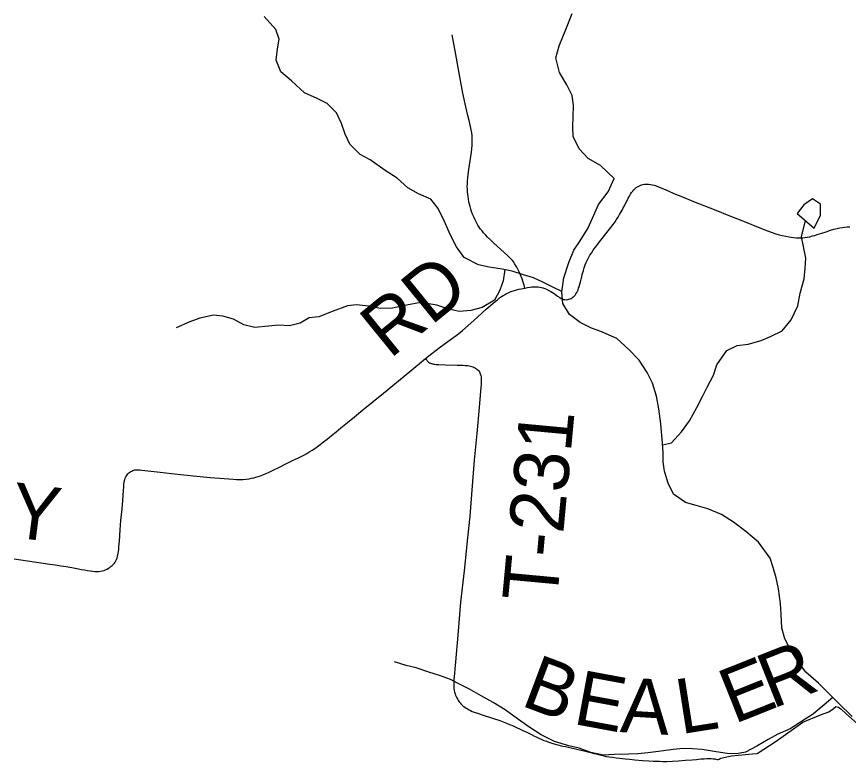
# Model space of a CAD drawing. Extents: x 1451455 to 1749751, y 218250 to 574981.
# Drawn here: x 1587271 to 1591819, y 293624 to 297697 of the extents above; entities that cross this region are included whole.
import ezdxf

# ---------------------------------------------------------------- set-up
doc = ezdxf.new("R2010")
doc.units = 0
for name, color, linetype in [('GM_X_Minor_Lake', 7, 'Continuous'), ('GM_X_Minor_River', 7, 'Continuous'), ('GM_X_Township_Road', 7, 'Continuous'), ('GM_X_Township_Road_Text', 7, 'Continuous'), ('GM_X_Township_ROW', 7, 'Continuous')]:
    doc.layers.add(name, color=color, linetype=linetype)

msp = doc.modelspace()

# ---------------------------------------------------------------- linework, layer by layer
at = {"layer": 'GM_X_Minor_Lake'}
for points in [[(1591632, 296539.6), (1591666.9, 296611.2), (1591665.7, 296671.3), (1591622, 296699.9), (1591575.6, 296668.5), (1591538.9, 296621)], [(1591538.9, 296621), (1591632, 296539.6)]]:
    msp.add_lwpolyline(points, dxfattribs=at)
at = {"layer": 'GM_X_Minor_River'}
for points in [[(1591840, 293869.1), (1591764.9, 293942.1), (1591707.5, 293999), (1591656.2, 294051.7), (1591586.8, 294110.7), (1591543.5, 294167.3), (1591500.4, 294237.9), (1591471.1, 294294.4), (1591455.8, 294352.6), (1591450.8, 294428.7), (1591447.5, 294486.8), (1591436.5, 294567), (1591423.3, 294627.2), (1591408, 294683.5), (1591390.6, 294735.8), (1591327.7, 294822.7), (1591258.4, 294881.6), (1591191, 294932.6), (1591125.4, 294973.5), (1591049.8, 295004.5), (1590986, 295023.4), (1590928.1, 295040.2), (1590862.6, 295085.1), (1590833.4, 295145.5), (1590814.2, 295211.8), (1590806.8, 295262), (1590805.5, 295312), (1590802.1, 295364.1), (1590793.5, 295470.3), (1590782.5, 295552.5), (1590769.4, 295620.7), (1590748.3, 295693), (1590719, 295751.5), (1590675.8, 295818.1), (1590618.5, 295876.9), (1590553.2, 295935.8), (1590465.7, 295975), (1590413.9, 295993.7), (1590352.2, 296024.6), (1590294.7, 296067.4), (1590257.4, 296127.9), (1590252.3, 296192), (1590263.2, 296267.9), (1590290.3, 296351.6), (1590317.2, 296419.3), (1590351.9, 296470.8), (1590394.8, 296538.3), (1590419.6, 296594), (1590452.6, 296669.6), (1590505.5, 296738.9), (1590538.5, 296812.5), (1590463.3, 296883.6), (1590395.7, 296920.5), (1590346.4, 296973.2), (1590313.2, 297041.7), (1590311.9, 297093.7), (1590314.6, 297149.7), (1590315.4, 297211.7), (1590308.1, 297265.8), (1590278.8, 297324.3), (1590239.6, 297390.8), (1590218.6, 297471.1), (1590237.5, 297536.9), (1590274.7, 297626.5), (1590307.8, 297714.1)], [(1590252.5, 296193.5), (1590202.5, 296216.7), (1590148.8, 296245.4), (1590097.1, 296268.1), (1590043.2, 296284.9), (1589981.5, 296305.7), (1589925.5, 296316.5), (1589855.6, 296327.4), (1589795.7, 296340.2), (1589718.2, 296379.3), (1589676.9, 296437.9), (1589643.7, 296502.4), (1589608.7, 296580.9), (1589575.5, 296647.3), (1589536.1, 296697.9), (1589468.4, 296728.8), (1589410.8, 296761.6), (1589351.4, 296814.4), (1589285.9, 296855.3), (1589204.6, 296914.5), (1589148.9, 296943.2), (1589093.6, 297000), (1589068.2, 297054.4), (1589047, 297112.7), (1589019.7, 297171.1), (1588968.3, 297221.8), (1588914.6, 297248.5), (1588844.9, 297279.5), (1588773.7, 297346.5), (1588716.3, 297395.2), (1588691.1, 297459.6), (1588697.9, 297521.5), (1588706.6, 297573.5), (1588689.3, 297627.7), (1588624.1, 297698.6)], [(1590802.7, 295355.2), (1590852.2, 295365.4), (1590907, 295426.7), (1590949.8, 295486.2), (1590990.8, 295559.7), (1591021.6, 295619.3), (1591048.3, 295675), (1591081.2, 295736.6), (1591099.9, 295792.4), (1591155, 295871.7), (1591211.4, 295898.9), (1591271.5, 295906.1), (1591341.8, 295925.2), (1591392.2, 295948.5), (1591456.6, 295977.7), (1591505.4, 296039.1), (1591542.4, 296114.6), (1591555.3, 296184.5), (1591576.3, 296262.2), (1591583.1, 296322.2), (1591585.8, 296376.2), (1591572.6, 296440.4), (1591563.3, 296492.5), (1591583.8, 296581.7)], [(1589940.9, 296313.5), (1589930.7, 296252.4), (1589914, 296200.6), (1589883.3, 296146.9), (1589816.7, 296105.8), (1589754.5, 296090.6), (1589690.3, 296083.5), (1589628.5, 296098.3), (1589568.7, 296119.1), (1589480.8, 296134.3), (1589402.5, 296119.4), (1589326.3, 296102.4), (1589260.2, 296101.3), (1589194.3, 296114.2), (1589130.3, 296121), (1589080.2, 296115.7), (1589001.8, 296086.8), (1588923.3, 296055.8), (1588871.2, 296050.5), (1588820.7, 296021.1), (1588762.5, 296005.9), (1588702.5, 296008.7), (1588648.4, 296003.5), (1588574.2, 295996.5), (1588514.3, 296011.3), (1588456.7, 296042), (1588398.8, 296058.8), (1588346.9, 296063.5), (1588272.6, 296048.5), (1588218.3, 296027.2), (1588143.8, 295994.2)], [(1591734.4, 293972.3), (1591628, 293884), (1591557.4, 293838.9), (1591500.8, 293801.6), (1591432.4, 293772.5), (1591380, 293743.2), (1591317.4, 293706), (1591257, 293674.8), (1591206.8, 293665.5), (1591156.8, 293666.1), (1591096.8, 293675), (1591018.9, 293688), (1590967, 293692.7), (1590914.9, 293693.4), (1590860.8, 293688.1), (1590780.6, 293677.2), (1590722.4, 293670), (1590668.3, 293664.7), (1590616.3, 293663.4), (1590538.1, 293660.5), (1590480, 293657.3), (1590410.2, 293672.2), (1590346.4, 293695.1), (1590290.5, 293707.9), (1590212.8, 293732.9), (1590139.2, 293768), (1590077.6, 293808.8), (1590010.1, 293855.8), (1589942.7, 293904.7), (1589877.2, 293945.6), (1589811.6, 293982.5), (1589748, 294019.4), (1589696.3, 294044.1), (1589642.6, 294070.9), (1589582.8, 294093.7), (1589525, 294112.5), (1589455.2, 294135.4), (1589401.3, 294148.2), (1589337.5, 294169)]]:
    msp.add_lwpolyline(points, dxfattribs=at)
at = {"layer": 'GM_X_Township_Road'}
for points in [[(1590049.5, 296212.7), (1590046.3, 296228), (1590043.2, 296239.3), (1590039.7, 296250.6), (1590035.4, 296262.7), (1590030.2, 296274.9), (1590024.1, 296288.8), (1590018.5, 296301.8), (1590011.9, 296316.1), (1590005.9, 296327.4), (1589999.4, 296338.3), (1589994.2, 296346.9), (1589989.4, 296353.9), (1589983.8, 296361.3), (1589977.2, 296368.6), (1589969.9, 296376), (1589954.2, 296390.8), (1589936.9, 296406.8), (1589880.4, 296457.2), (1589863.1, 296473.7), (1589846.6, 296490.2), (1589836.6, 296501.4), (1589824.4, 296514.5), (1589815.8, 296524.9), (1589807.5, 296535.3), (1589801, 296544.8), (1589793.6, 296557), (1589785.8, 296571.7), (1589778.9, 296586.1), (1589771.5, 296601.7), (1589764.6, 296616.9), (1589758.9, 296631.7), (1589754.1, 296644.3), (1589750.2, 296658.1), (1589747.2, 296671.2), (1589744.2, 296684.6), (1589741.6, 296699.4), (1589739.8, 296713.3), (1589737, 296739.4), (1589735.9, 296754.1), (1589735.3, 296768.8), (1589735.5, 296782.7), (1589736.2, 296798.2), (1589737.6, 296814.4), (1589739.4, 296833.5), (1589742.9, 296860.4), (1589746.8, 296885.6), (1589750.6, 296908.7)], [(1590049.5, 296212.7), (1590064.8, 296215.4), (1590079.2, 296217.4), (1590088.9, 296218.4), (1590095, 296218.8), (1590100.7, 296219.2), (1590111.1, 296219.2), (1590122.3, 296218.8), (1590131, 296217.9), (1590140.1, 296216.2), (1590148.8, 296213.6), (1590158.8, 296210.1), (1590169.2, 296205.8), (1590180.9, 296199.7), (1590192.2, 296193.2), (1590210, 296181.9), (1590229.1, 296168.9), (1590240.4, 296161.1), (1590249.1, 296155.9), (1590255.6, 296152.8), (1590261.7, 296150.7), (1590269.1, 296149.3), (1590276.9, 296148.9), (1590284.3, 296149.3), (1590291.2, 296151.1), (1590296.8, 296153.2), (1590302.9, 296156.3), (1590308.1, 296159.3), (1590313.7, 296163.7), (1590319.4, 296168.4), (1590324.2, 296173.7), (1590329.4, 296180.1), (1590333.7, 296187.5), (1590337.2, 296195.4), (1590340.7, 296203.6), (1590343.7, 296211.8), (1590346.3, 296221), (1590350.2, 296234), (1590353.7, 296247), (1590357.6, 296261.3), (1590360.6, 296273.5), (1590364.1, 296286.9), (1590369.8, 296308.5), (1590374.1, 296323.4), (1590380.2, 296339.5), (1590385.8, 296352.9), (1590391.7, 296366.5), (1590397.5, 296377.7), (1590405.8, 296392.2), (1590413.6, 296404.1), (1590423.7, 296419.4), (1590434.8, 296434.5), (1590443.5, 296446.2), (1590452.8, 296458.6), (1590505.2, 296525.5), (1590520.3, 296544.3), (1590532.1, 296559.5), (1590542.9, 296574.7), (1590551.2, 296587.3), (1590559.4, 296600.8), (1590568.1, 296614.6), (1590576.3, 296628.9), (1590582, 296638.9), (1590588.3, 296651.2), (1590594.6, 296662.8), (1590600.7, 296675), (1590607.2, 296688.4), (1590615.4, 296704), (1590621.9, 296715.7), (1590625.4, 296721.8), (1590628.4, 296727), (1590633.6, 296734.8), (1590639.7, 296742.6), (1590645.8, 296749.6), (1590652.7, 296756.6), (1590659.3, 296761.8), (1590666.2, 296766.5), (1590673.1, 296770.4), (1590680.9, 296774.3), (1590688.3, 296777), (1590695.2, 296778.7), (1590703.5, 296780), (1590711.3, 296780.9), (1590719.6, 296781.3), (1590726.5, 296780.9), (1590736.1, 296779.6), (1590746.5, 296777.8), (1590757.7, 296775.2), (1590768.6, 296771.7), (1590781.2, 296767), (1590794.2, 296761.3), (1590808.1, 296755.2), (1590833.3, 296744.4), (1590864.5, 296730.5), (1590911.8, 296711), (1590972.6, 296685.8), (1591093.9, 296638.1), (1591164.4, 296610.3), (1591236.9, 296581.6), (1591344.1, 296538.7), (1591377.1, 296525.2), (1591402.3, 296515.7), (1591421.4, 296509.6), (1591440.1, 296504.4), (1591457.4, 296500), (1591476.1, 296495.7), (1591493, 296492.6), (1591505.6, 296490.9), (1591519.1, 296489.2), (1591536, 296487.9), (1591546.8, 296487.5), (1591558.5, 296487), (1591569.4, 296487.5), (1591581.1, 296488.7), (1591593.3, 296490.5), (1591608.5, 296493.5), (1591623.2, 296497.4), (1591634.9, 296500.9), (1591648.8, 296505.2), (1591674, 296513.5), (1591696.6, 296520.9), (1591721.3, 296528.7), (1591740, 296534.3), (1591757.8, 296539.1), (1591771.7, 296542.2), (1591785.9, 296544.6), (1591797.7, 296546.1), (1591811.9, 296547.4), (1591826.8, 296547.8)], [(1589506.8, 295828), (1589524.3, 295842.5), (1589581.2, 295885.4), (1589608.5, 295905.8), (1589642, 295929.7), (1589662.3, 295944), (1589674.9, 295953.1), (1589689.7, 295964), (1589708.3, 295979.6), (1589771.3, 296036), (1589839, 296097.2), (1589874.6, 296127.6), (1589887.6, 296138.4), (1589899.8, 296148.8), (1589911.9, 296158.4), (1589922.8, 296166.2), (1589931.4, 296171.9), (1589938.4, 296176.2), (1589949.7, 296182.3), (1589959.6, 296187.1), (1589970.5, 296191.8), (1589980.9, 296195.7), (1589993.5, 296199.6), (1590004.8, 296203.1), (1590016.5, 296206.2), (1590030, 296209.2), (1590049.5, 296212.7)], [(1587257.8, 294732.4), (1587452, 294702.7), (1587481.7, 294698.2), (1587513.9, 294693.6), (1587543, 294688.8), (1587572.5, 294683.8), (1587601.3, 294678.4), (1587626.5, 294674), (1587643.1, 294671.1), (1587659.4, 294668.1), (1587673.5, 294666), (1587687.1, 294664.5), (1587699.7, 294663.1), (1587710.1, 294662.8), (1587720.5, 294662.8), (1587730.1, 294663.6), (1587739.6, 294665.4), (1587749.2, 294667.9), (1587757.4, 294671), (1587766.9, 294675.8), (1587774.2, 294679.8), (1587780.8, 294684.9), (1587788.7, 294690.5), (1587794.3, 294695.3), (1587800.8, 294701.8), (1587806, 294707.9), (1587809.9, 294714), (1587813.8, 294721.4), (1587816.9, 294728.7), (1587820.3, 294737.4), (1587822.5, 294744.8), (1587825.1, 294753.5), (1587826.8, 294761.7), (1587828.6, 294772.1), (1587829.8, 294784.6), (1587830.7, 294799), (1587833, 294827.2), (1587837.2, 294891), (1587841.6, 294941.4), (1587847.7, 295005.6), (1587851.6, 295050.3), (1587855, 295105.2), (1587856.8, 295125.4), (1587858.1, 295139.8), (1587859.8, 295151.9), (1587862.5, 295165.3), (1587865.2, 295173.3), (1587868.1, 295180.1), (1587871.6, 295186.2), (1587875.9, 295191.8), (1587880.2, 295196.6), (1587884.6, 295201), (1587890.2, 295205.3), (1587895.8, 295208.8), (1587900.6, 295211.8), (1587906.3, 295214.4), (1587912.8, 295216.6), (1587918.4, 295217.9), (1587924.5, 295218.3), (1587929.7, 295218.3), (1587936.4, 295218.3), (1587944.4, 295217.7), (1587955.3, 295216.6), (1587988.8, 295212.7), (1588056.9, 295204.9), (1588118.1, 295198.4), (1588185.8, 295191), (1588257, 295183.6), (1588329.9, 295177.1), (1588406.3, 295170.6), (1588432.3, 295168.4), (1588455.7, 295166.7), (1588473.1, 295165.8), (1588490.5, 295165.8), (1588507.4, 295166.2), (1588525.6, 295167.5), (1588542.1, 295169.7), (1588555.6, 295171.9), (1588568.6, 295174.9), (1588579.4, 295177.5), (1588591.2, 295181), (1588604.2, 295185.8), (1588621.6, 295192.7), (1588635.9, 295198.8), (1588651.9, 295205.7), (1588673.2, 295215.7), (1588704, 295230.9), (1588743.1, 295250.9), (1588780, 295268.7), (1588812.5, 295284.3), (1588826.8, 295291.2), (1588840.7, 295298.2), (1588857.2, 295307.3), (1588874.6, 295317.7), (1588887.2, 295326), (1588901.1, 295335.5), (1588915.4, 295345.5), (1588930.6, 295357.2), (1588948.4, 295371.1), (1588968.3, 295386.7), (1588990.9, 295405), (1589017.8, 295426.6), (1589043.4, 295447.5), (1589079.5, 295477), (1589118.1, 295508.2), (1589163.7, 295546), (1589277.8, 295637.6), (1589420.6, 295757), (1589506.8, 295828)], [(1589506.8, 295828), (1589510, 295822.4), (1589513.3, 295817.4), (1589516.3, 295813.6), (1589519.6, 295810.4), (1589523, 295807.1), (1589529.2, 295803.1), (1589533.6, 295801.3), (1589539.1, 295799.4), (1589545.4, 295797.8), (1589551.3, 295796.5), (1589557.6, 295795.6), (1589565.8, 295794.8), (1589578, 295794), (1589614.9, 295792.2), (1589680.6, 295790.7), (1589712.3, 295789.9), (1589723.1, 295789.4), (1589731.6, 295788.9), (1589739.1, 295788.5), (1589746.2, 295787.6), (1589753.7, 295785.9), (1589760.3, 295784.1), (1589767, 295781.9), (1589773.5, 295778.6), (1589780.4, 295774.7), (1589785.7, 295771.2), (1589790, 295767.7), (1589794.8, 295762.9), (1589797.8, 295759), (1589801.3, 295753.8), (1589803.9, 295748.6), (1589806.5, 295742.6), (1589808.7, 295734.7), (1589810.4, 295726.5), (1589811.3, 295718.2), (1589811.7, 295707.8), (1589811.7, 295696.5), (1589810.8, 295684.4), (1589809.9, 295669.2), (1589807.8, 295648.8), (1589799.3, 295558.7), (1589786.9, 295417.9), (1589773.4, 295271.7), (1589761.4, 295131.3), (1589749.2, 294964.8), (1589737, 294846.7), (1589717.9, 294665.6), (1589698.9, 294493.8), (1589682.8, 294314.2), (1589670.6, 294167.2), (1589666.7, 294129.5), (1589664.6, 294104.7), (1589662.4, 294073.3), (1589661.5, 294057), (1589661.1, 294045.7), (1589661.5, 294034.4), (1589662.4, 294022.7), (1589663.7, 294013.2), (1589665.9, 294001.9), (1589668.2, 293993.6), (1589670.9, 293985.8), (1589673.7, 293979.3), (1589678, 293971.1), (1589683, 293962.8), (1589687.7, 293954.9), (1589691.3, 293949.6), (1589696.6, 293943.4), (1589700.6, 293938.9), (1589706, 293933.3), (1589711.6, 293927.9), (1589721.2, 293920.7), (1589729.2, 293915.5), (1589737.3, 293910.3), (1589745.1, 293905.5), (1589753.3, 293901.2), (1589762, 293897.3), (1589773.7, 293892.9), (1589790.3, 293887.3), (1589827.6, 293874.5), (1589913.9, 293846.5), (1589932.2, 293839.5), (1589949.5, 293832.6), (1589966.9, 293825.7), (1589986.8, 293817.4), (1590004.6, 293809.6), (1590025, 293800.5), (1590043.2, 293791.4), (1590056.3, 293784.8), (1590071, 293777.6), (1590085.8, 293770.5), (1590102.3, 293762.3), (1590115.3, 293755.8), (1590127, 293750.4), (1590140, 293744.5), (1590154, 293738.7), (1590167.8, 293733.7), (1590181, 293729.1), (1590196.9, 293723.7), (1590216.4, 293717.6), (1590230.3, 293713.7), (1590243.2, 293710.5), (1590257.2, 293707.6), (1590271.6, 293704.6), (1590286.7, 293701.5), (1590303.8, 293698), (1590326.1, 293692.8), (1590348.4, 293687.6), (1590374, 293681.7), (1590394, 293676.3), (1590410.9, 293672), (1590427.7, 293667.5), (1590440.3, 293664.1), (1590460.8, 293659), (1590476.8, 293655.1), (1590495.1, 293651.2), (1590511.1, 293648.6), (1590529.9, 293646), (1590548.5, 293643.4), (1590568.8, 293640.7), (1590599.2, 293637.7), (1590624.3, 293635.4), (1590651.3, 293632.9), (1590693, 293629), (1590728.3, 293626.8), (1590751.8, 293625.5), (1590770.8, 293624.5), (1590786.7, 293624.1), (1590803.1, 293623.7), (1590825.7, 293623.7), (1590857.9, 293625.1), (1590890, 293627.3), (1590927.4, 293629.9), (1590964.7, 293632.5), (1590989, 293634.7), (1591012, 293636.8), (1591030.7, 293638.2), (1591045.4, 293639), (1591059.3, 293639.5), (1591068.4, 293639), (1591078.8, 293638.2), (1591088.9, 293636.9), (1591094.9, 293635.5), (1591100.5, 293634.3), (1591106.8, 293634.7), (1591112.3, 293636.4), (1591117.5, 293639.5), (1591121.3, 293641.4), (1591179.3, 293653.6), (1591293.8, 293664.3)], [(1591293.8, 293664.3), (1591320.6, 293666.8), (1591424.7, 293733.3), (1591570.6, 293838.6), (1591667.2, 293878.3), (1591711.9, 293894.5), (1591736.3, 293910.8), (1591749.5, 293923), (1591764.8, 293919.9), (1591779.4, 293909.2), (1591804.4, 293886.4), (1591869.5, 293828.4)]]:
    msp.add_lwpolyline(points, dxfattribs=at)
at = {"layer": 'GM_X_Township_ROW'}
msp.add_lwpolyline([(1589750.6, 296908.7), (1589750.7, 296909.4), (1589754.1, 296932.9), (1589757.6, 296956.6), (1589759.8, 296974.5), (1589761.1, 296993.6), (1589762.4, 297011), (1589762.8, 297025.8), (1589761.9, 297045.3), (1589759.8, 297061.8), (1589756.8, 297077.8), (1589752.8, 297096.5), (1589749, 297113.4), (1589745, 297129.9), (1589738.9, 297155.5), (1589727.7, 297203.2), (1589711.2, 297278.8), (1589694.7, 297367.3), (1589672, 297489.8), (1589652.1, 297596.9)], dxfattribs=at)

# ---------------------------------------------------------------- texts
at = {"layer": 'GM_X_Township_Road_Text'}
for s, rotation, p in [('RD', 39.1192, (1589311.1, 295820.9)), ('T-231', 84.679, (1590224.6, 294488.3)), ('Y', 352.5991, (1587224.7, 294853.6)), ('R', 21.6086, (1591401.7, 293909.1)), ('B', 339.438, (1590020.6, 293931.9)), ('E', 21.7059, (1591193.4, 293826.2)), ('E', 349.5258, (1590306.8, 293829.9)), ('A', 356.595, (1590567.5, 293784.2)), ('L', 8.9671, (1590901.6, 293772))]:
    msp.add_text(s, height=300, rotation=rotation, dxfattribs=at).set_placement(p)

doc.saveas('drawing.dxf')
